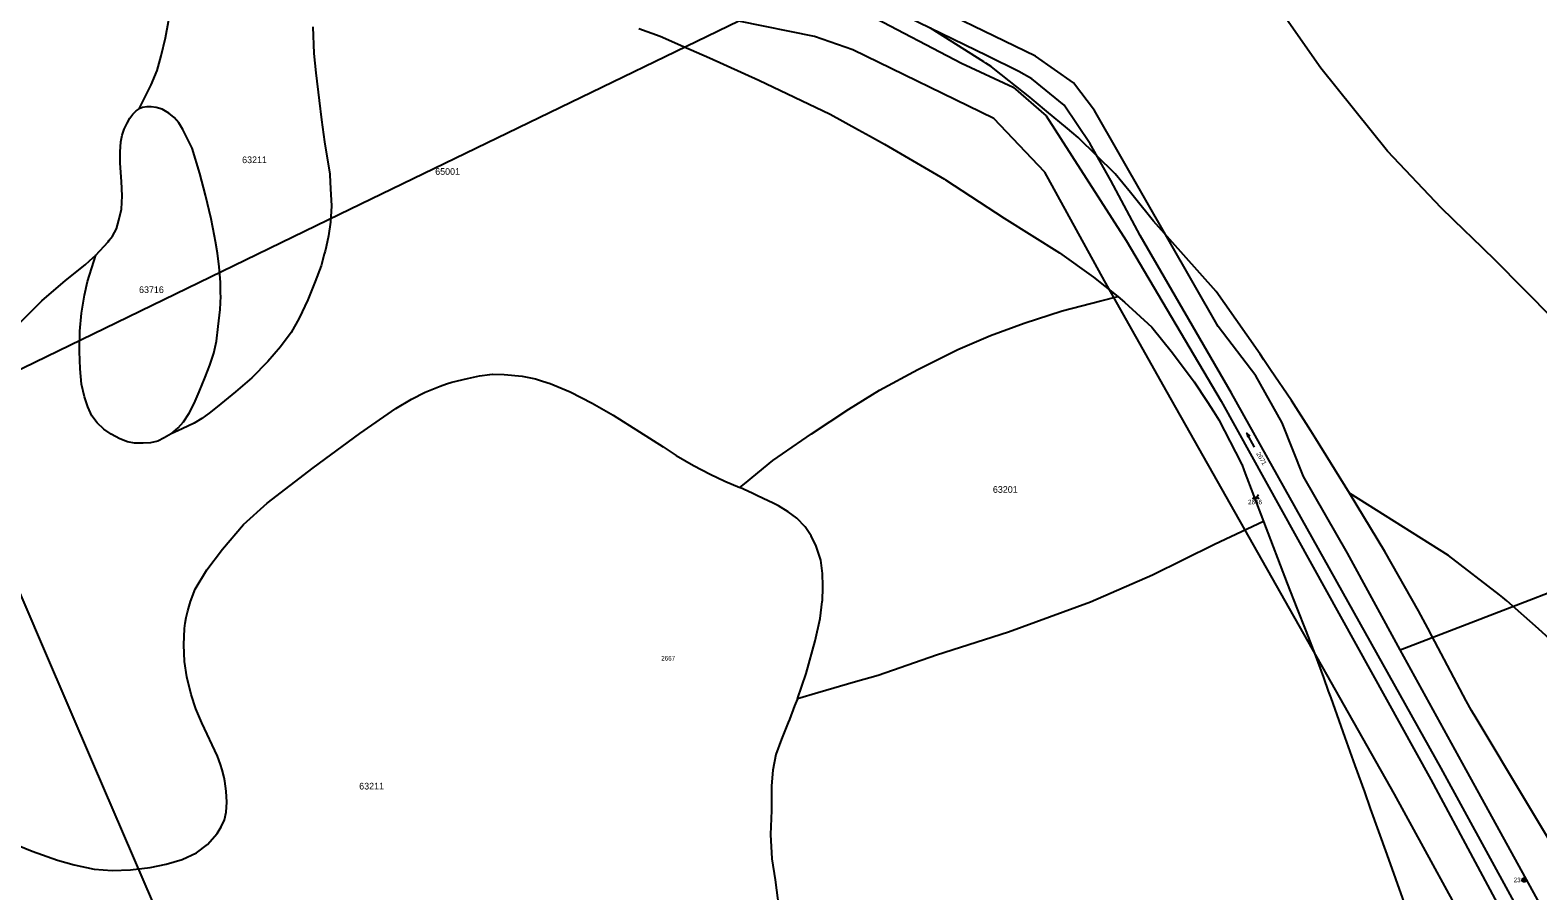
# Model space of a CAD drawing. Extents: x -546762 to -540209, y -1046851 to -1035694.
# Drawn here: x -542107 to -541542, y -1038827 to -1038504 of the extents above; entities that cross this region are included whole.
import ezdxf

# ---------------------------------------------------------------- set-up
doc = ezdxf.new("R2010")
doc.units = 0
for name, color, linetype in [('Vrstva 1', 7, 'Continuous'), ('Vrstva 17', 7, 'Continuous'), ('Vrstva 18', 7, 'Continuous'), ('Vrstva 24', 7, 'Continuous'), ('Vrstva 25', 7, 'Continuous'), ('Vrstva 52', 7, 'Continuous'), ('Vrstva 53', 7, 'Continuous')]:
    doc.layers.add(name, color=color, linetype=linetype)

msp = doc.modelspace()

# ---------------------------------------------------------------- linework, layer by layer
at = {"layer": 'Vrstva 1'}
for points in [[(-541748.26, -1038513.34), (-541791.07, -1038492.6)], [(-541730.12, -1038513.51), (-541780.32, -1038489.07)], [(-541792.79, -1038497.84), (-541757.91, -1038516.08)], [(-541841.44, -1038500.31), (-541991.19, -1038572.93)], [(-541813.12, -1038506.14), (-541841.44, -1038500.31)], [(-541798.72, -1038511.12), (-541813.12, -1038506.14)], [(-541745.78, -1038536.92), (-541798.72, -1038511.12)], [(-541757.91, -1038516.08), (-541738.54, -1038525.08)], [(-541736.38, -1038519.26), (-541748.26, -1038513.34)], [(-541715.94, -1038523.49), (-541730.12, -1038513.51)], [(-541731.51, -1038522.03), (-541736.38, -1038519.26)], [(-541719.47, -1038531.94), (-541731.51, -1038522.03)], [(-541738.54, -1038525.08), (-541726.16, -1038535.91)], [(-541708.02, -1038533.92), (-541715.94, -1038523.49)], [(-541709.68, -1038546.42), (-541719.47, -1038531.94)], [(-541661.65, -1038614.99), (-541708.02, -1038533.92)], [(-541726.69, -1038556.98), (-541745.78, -1038536.92)], [(-541726.16, -1038535.91), (-541696.15, -1038582.68)], [(-541701.9, -1038560.12), (-541709.68, -1038546.42)], [(-541721.84, -1038565.89), (-541726.69, -1038556.98)], [(-541690.92, -1038580.84), (-541701.9, -1038560.12)], [(-541704.31, -1038597.79), (-541721.84, -1038565.89)], [(-541991.19, -1038572.93), (-542140.94, -1038645.54)], [(-541696.15, -1038582.68), (-541660.48, -1038643)], [(-541656.69, -1038639.93), (-541690.92, -1038580.84)], [(-541680.71, -1038639.57), (-541704.31, -1038597.79)], [(-541647.55, -1038633.48), (-541661.65, -1038614.99)], [(-541637.59, -1038651.06), (-541647.55, -1038633.48)], [(-541595.51, -1038790.38), (-541680.71, -1038639.57)], [(-541578.01, -1038780.71), (-541656.69, -1038639.93)], [(-541660.48, -1038643), (-541581.9, -1038784.9)], [(-541629.59, -1038671.24), (-541637.59, -1038651.06)], [(-542102.16, -1038735.71), (-542130.32, -1038670.22)], [(-541613.09, -1038700.05), (-541629.59, -1038671.24)], [(-541593.42, -1038736.24), (-541489.42, -1038696.2)], [(-541593.42, -1038736.24), (-541613.09, -1038700.05)], [(-542083.46, -1038779.2), (-542102.16, -1038735.71)], [(-541568.56, -1038781.24), (-541593.42, -1038736.24)], [(-542038.89, -1038882.85), (-542083.46, -1038779.2)], [(-541543.25, -1038844.31), (-541578.01, -1038780.71)], [(-541506.89, -1038893.6), (-541568.56, -1038781.24)], [(-541581.9, -1038784.9), (-541548.61, -1038846.92)], [(-541562.11, -1038851.5), (-541595.51, -1038790.38)]]:
    msp.add_lwpolyline(points, dxfattribs=at)
at = {"layer": 'Vrstva 24'}
for radius in [0.75, 0.1]:
    msp.add_circle((-541546.84, -1038822.61), radius, dxfattribs=at)
at = {"layer": 'Vrstva 25'}
for p, q in [((-541648.49, -1038677.94), (-541647.49, -1038679.44)), ((-541647.49, -1038679.44), (-541646.49, -1038677.94))]:
    msp.add_line(p, q, dxfattribs=at)
for points in [[(-541647.99, -1038660.19), (-541650.85, -1038654.91), (-541650.57, -1038656.47)], [(-541650.85, -1038654.91), (-541649.7, -1038655.99)]]:
    msp.add_lwpolyline(points, dxfattribs=at)
for centre in [(-541648.39, -1038679.39), (-541646.59, -1038679.39)]:
    msp.add_circle(centre, 0.112, dxfattribs=at)
at = {"layer": 'Vrstva 52'}
for points in [[(-542066.35, -1038533.29), (-542061.83, -1038524.26), (-542059.59, -1038518.88), (-542058.09, -1038513.35), (-542056.45, -1038506.63), (-542055.4, -1038500.5), (-542055.27, -1038495.33), (-542055.25, -1038494.67), (-542054.98, -1038488.06), (-542054.96, -1038487.5)], [(-541535.86, -1038612.21), (-541557.82, -1038589.98), (-541566.48, -1038581.53), (-541569.1, -1038578.98), (-541577.95, -1038570.36), (-541598.07, -1038549.18), (-541623.17, -1038518.05), (-541638.67, -1038495.9)], [(-542001.29, -1038502.45), (-542000.84, -1038512.46), (-542000.09, -1038519.78), (-541998.9, -1038530.1), (-541998, -1038537.42), (-541996.81, -1038545.64), (-541994.91, -1038557.8), (-541994.87, -1038558.04), (-541994.57, -1038563.33), (-541994.27, -1038569.61), (-541994.57, -1038575.73), (-541995.31, -1038580.97), (-541996.28, -1038585.03), (-541996.66, -1038586.64), (-541996.96, -1038587.76), (-541998.15, -1038592.17), (-542000.39, -1038598), (-542003.08, -1038604.88), (-542006.37, -1038611.75), (-542009.36, -1038617.13), (-542013.39, -1038622.51), (-542018.17, -1038628.04), (-542024.14, -1038634.17), (-542030.27, -1038639.4), (-542037.14, -1038645.08), (-542040.15, -1038647.46), (-542042.84, -1038649.51), (-542045.81, -1038651.22), (-542050.25, -1038653.37), (-542054.35, -1038655.19)], [(-541878.92, -1038503.11), (-541871, -1038505.99), (-541862.15, -1038509.86), (-541852.44, -1038514.1), (-541833.88, -1038522.47), (-541807.22, -1038535.28), (-541796.57, -1038541.16), (-541792.42, -1038543.45), (-541786.83, -1038546.53), (-541764.35, -1038559.6), (-541763.86, -1038559.92), (-541741.87, -1038574.25), (-541721.22, -1038587.33), (-541708.38, -1038596.37), (-541699.29, -1038603.72)], [(-541612.42, -1038677.5), (-541624.96, -1038657.1), (-541626.87, -1038654.1), (-541634.11, -1038642.71), (-541641.97, -1038631.16), (-541644.51, -1038627.42), (-541645.91, -1038625.37), (-541650.92, -1038618.21), (-541659.18, -1038606.41), (-541662.38, -1038601.84), (-541685.9, -1038575.42), (-541693.05, -1038566.58), (-541694.57, -1038564.69), (-541700.28, -1038557.64), (-541714.14, -1038544.04), (-541716.54, -1038542.04), (-541718.17, -1038540.68), (-541726.01, -1038534.14), (-541729.92, -1038530.88), (-541731.39, -1038529.65), (-541732.3, -1038528.93), (-541745.37, -1038518.51), (-541746.81, -1038517.36), (-541748.77, -1038516.12), (-541749.57, -1038515.61), (-541769.53, -1038502.98)], [(-542082.67, -1038588.19), (-542078.04, -1038583.11), (-542077.59, -1038582.51), (-542076.44, -1038580.99), (-542074.9, -1038578.26), (-542073.96, -1038575.01), (-542073.03, -1038570.91), (-542072.77, -1038565.96), (-542073.05, -1038560.52), (-542073.47, -1038553.68), (-542073.47, -1038549.41), (-542073.28, -1038545.68), (-542072.79, -1038543.1), (-542072.01, -1038540.9), (-542070.94, -1038538.61), (-542069.91, -1038536.75), (-542068.79, -1038535.24), (-542067.57, -1038534.07), (-542066.35, -1038533.29)], [(-542054.35, -1038655.19), (-542051.72, -1038652.94), (-542049.77, -1038650.65), (-542047.67, -1038647.48), (-542045.75, -1038643.78), (-542043.88, -1038639.51), (-542041.57, -1038633.96), (-542039.86, -1038629.43), (-542038.41, -1038624.91), (-542037.43, -1038620.38), (-542036.75, -1038614.91), (-542035.98, -1038608.6), (-542035.81, -1038603.56), (-542035.83, -1038602.52), (-542035.88, -1038599.22), (-542035.9, -1038598.26), (-542036.32, -1038592.54), (-542037.01, -1038587.42), (-542037.74, -1038583.05), (-542038.12, -1038581.06), (-542039.38, -1038574.53), (-542041.48, -1038565.71), (-542043.57, -1038557.49), (-542046.55, -1038548.08), (-542050.01, -1038541.05), (-542051.53, -1038538.56), (-542053.23, -1038536.56), (-542055.28, -1038534.9), (-542057.82, -1038533.34), (-542059.96, -1038532.75), (-542061.87, -1038532.46), (-542063.52, -1038532.51), (-542065.18, -1038532.8), (-542066.35, -1038533.29)], [(-542126.79, -1038628.35), (-542113.03, -1038615.32), (-542111.75, -1038614.11), (-542110.8, -1038613.16), (-542102.93, -1038605.29), (-542093.97, -1038597.67), (-542086.7, -1038591.78), (-542084.99, -1038590.26), (-542082.67, -1038588.19)], [(-542064.93, -1038658.75), (-542068.2, -1038658.75), (-542070.74, -1038658.26), (-542073.62, -1038657.14), (-542076.93, -1038655.28), (-542079.62, -1038653.48), (-542082.15, -1038651.14), (-542084.1, -1038648.45), (-542085.61, -1038645.04), (-542086.88, -1038641.33), (-542088, -1038636.55), (-542088.57, -1038630.76), (-542088.74, -1038624.27), (-542088.65, -1038616.75), (-542087.97, -1038609.95), (-542087.89, -1038609.15), (-542086.86, -1038603.17), (-542085.75, -1038598.05), (-542083.41, -1038590.57), (-542082.67, -1038588.19)], [(-541774.35, -1038631.03), (-541759.26, -1038623.56), (-541747.01, -1038618.33), (-541734.47, -1038613.7), (-541720.13, -1038609.06), (-541705.64, -1038605.33), (-541699.29, -1038603.72)], [(-541699.29, -1038603.72), (-541696.73, -1038605.79), (-541686.57, -1038615.2), (-541678.81, -1038624.77), (-541670.59, -1038635.68), (-541665.82, -1038643.07), (-541663.28, -1038647), (-541661.33, -1038650.02), (-541652.97, -1038666.16), (-541652.8, -1038666.59), (-541651.86, -1038669.08), (-541644.6, -1038688.13)], [(-542123.76, -1038804.79), (-542106.58, -1038811.81), (-542097.02, -1038815.25), (-542090.75, -1038816.89), (-542083.28, -1038818.53), (-542076.56, -1038819.13), (-542069.69, -1038818.83), (-542062.22, -1038817.94), (-542056.24, -1038816.74), (-542050.27, -1038814.95), (-542044.89, -1038812.41), (-542040.71, -1038809.27), (-542037.12, -1038805.23), (-542035.57, -1038802.67), (-542034.37, -1038800.11), (-542033.77, -1038797.21), (-542033.52, -1038793.45), (-542033.69, -1038789.35), (-542034.2, -1038785.51), (-542034.51, -1038784.2), (-542035.23, -1038781.24), (-542035.9, -1038779.33), (-542037.02, -1038776.11), (-542042.83, -1038763.72), (-542045.18, -1038758.45), (-542046.83, -1038753.07), (-542048.47, -1038746.35), (-542049.37, -1038740.67), (-542049.66, -1038734.39), (-542049.37, -1038728.27), (-542049.08, -1038726.23), (-542048.77, -1038724.08), (-542048.13, -1038721.67), (-542047.42, -1038719), (-542047.11, -1038718.17), (-542045.33, -1038713.47), (-542041, -1038706.3), (-542035.18, -1038698.53), (-542027.26, -1038689.26), (-542018.32, -1038681.26), (-542001.14, -1038667.96), (-541983.66, -1038655.11), (-541970.07, -1038645.69), (-541964.26, -1038642.16), (-541959.13, -1038639.6), (-541956.55, -1038638.54), (-541953.5, -1038637.29), (-541951.05, -1038636.49), (-541949.06, -1038635.84), (-541943.26, -1038634.39), (-541938.73, -1038633.45), (-541934.85, -1038632.96), (-541933.95, -1038632.85), (-541933.86, -1038632.85), (-541929.52, -1038632.94), (-541922.69, -1038633.54), (-541917.74, -1038634.56), (-541915.03, -1038635.41), (-541912.27, -1038636.27), (-541904.68, -1038639.51), (-541896.48, -1038643.7), (-541888.63, -1038648.22), (-541878.65, -1038654.46), (-541869.85, -1038660.1), (-541864.91, -1038663.32), (-541858.43, -1038667.08), (-541852.2, -1038670.41), (-541846.73, -1038672.97), (-541841.02, -1038675.37)], [(-541841.02, -1038675.37), (-541838.66, -1038673.43), (-541836.49, -1038671.64), (-541828.72, -1038665.26), (-541814.23, -1038655.24), (-541800.19, -1038645.98), (-541788.69, -1038638.8), (-541774.35, -1038631.03)], [(-542054.35, -1038655.19), (-542056.98, -1038656.75), (-542059.42, -1038657.97), (-542062.11, -1038658.65), (-542064.93, -1038658.75)], [(-541819.48, -1038754.6), (-541816.19, -1038745.19), (-541812.76, -1038732.93), (-541810.89, -1038724.56), (-541810.15, -1038718.19), (-541810.12, -1038717.9), (-541809.95, -1038712.69), (-541809.96, -1038712.33), (-541810.12, -1038707.65), (-541810.72, -1038702.61), (-541812.42, -1038697.31), (-541814.3, -1038693.47), (-541816.6, -1038690.05), (-541819.68, -1038686.9), (-541822.92, -1038684.42), (-541826.59, -1038682.2), (-541828.78, -1038681.16), (-541830.18, -1038680.49), (-541834.68, -1038678.36), (-541836.49, -1038677.5), (-541841.02, -1038675.37)], [(-541380.04, -1039082.96), (-541381.79, -1039079.78), (-541401.05, -1039044.89), (-541404.1, -1039039.37), (-541435.69, -1038982.14), (-541438.3, -1038977.41), (-541440.84, -1038972.81), (-541451.59, -1038953.35), (-541488.19, -1038891.57), (-541490.98, -1038886.8), (-541524.83, -1038828.9), (-541527.04, -1038825.13), (-541527.53, -1038824.28), (-541564.9, -1038761.93), (-541566.67, -1038758.97), (-541568.59, -1038755.36), (-541581.53, -1038730.99), (-541583.02, -1038728.19), (-541586.54, -1038721.57), (-541599.08, -1038699.34), (-541612.42, -1038677.5)], [(-541447.04, -1038840.25), (-541461.88, -1038817.68), (-541487.5, -1038785.64), (-541514.29, -1038756.1), (-541538.6, -1038730.99), (-541541.54, -1038728.38), (-541553.37, -1038717.89), (-541554.81, -1038716.61), (-541556.16, -1038715.57), (-541575.2, -1038700.92), (-541612.42, -1038677.5)], [(-541644.6, -1038688.13), (-541662.96, -1038696.71), (-541686.22, -1038708.22), (-541709.48, -1038718.42), (-541740.33, -1038729.67), (-541767.25, -1038738.3), (-541789.21, -1038745.88), (-541797.63, -1038748.31), (-541811.86, -1038752.41)], [(-541644.6, -1038688.13), (-541635.81, -1038711.32), (-541632.16, -1038720.57), (-541628.77, -1038729.17), (-541625.09, -1038738.52), (-541622.16, -1038746.7), (-541620.35, -1038751.74), (-541619.43, -1038754.3), (-541614.12, -1038769.12), (-541610.35, -1038779.64), (-541606.8, -1038789.52), (-541604.58, -1038795.77), (-541598.43, -1038813.06)], [(-541811.86, -1038752.41), (-541819.48, -1038754.6)], [(-541819.48, -1038754.6), (-541820.51, -1038757.27), (-541822.47, -1038762.37), (-541822.92, -1038763.52), (-541825.43, -1038769.85), (-541827.52, -1038775.53), (-541828.71, -1038781.36), (-541829.16, -1038787.34), (-541829.16, -1038796.61), (-541829.61, -1038805.57), (-541829.01, -1038814.69)], [(-541829.01, -1038814.69), (-541827.82, -1038822.61), (-541826.47, -1038833.22), (-541824.99, -1038841.09), (-541822.75, -1038849.01), (-541821.92, -1038851.4), (-541820.47, -1038855.59), (-541820.06, -1038856.78)], [(-541598.43, -1038813.06), (-541591.9, -1038831.36)]]:
    msp.add_lwpolyline(points, dxfattribs=at)

# ---------------------------------------------------------------- texts
at = {"layer": 'Vrstva 17'}
msp.add_text('234', height=1.7, dxfattribs=at).set_placement((-541550.77, -1038823.46))
at = {"layer": 'Vrstva 18'}
msp.add_text('2671', height=1.7, rotation=300.2299, dxfattribs=at).set_placement((-541647.43, -1038662.64))
for s, p in [('2666', (-541650.42, -1038681.65)), ('2667', (-541870.56, -1038740.28))]:
    msp.add_text(s, height=1.7, dxfattribs=at).set_placement(p)
at = {"layer": 'Vrstva 53'}
for s, p in [('63211', (-542027.76, -1038553.64)), ('65001', (-541955.34, -1038558.02)), ('63716', (-542066.43, -1038602.39)), ('63201', (-541746.14, -1038677.35)), ('63211', (-541983.85, -1038788.67))]:
    msp.add_text(s, height=2.5, dxfattribs=at).set_placement(p)

doc.saveas('drawing.dxf')
